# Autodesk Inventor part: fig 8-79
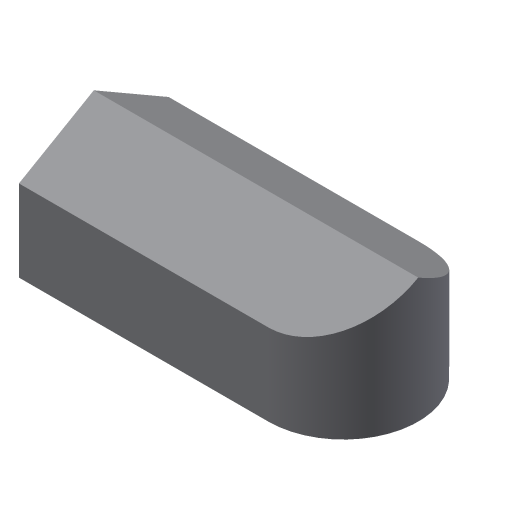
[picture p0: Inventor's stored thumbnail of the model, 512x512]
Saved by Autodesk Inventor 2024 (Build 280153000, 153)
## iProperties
Created: 2011-07
Part Number: fig 8-79
Material: Generic
Document SubType Name: Modeling
Designer: CadCim
Density: 1 g/cm^3
Appearance: Default
Author: CadCim
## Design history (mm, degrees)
sketch "Sketch1"
  geometry: L1 (-16, 5)-(-16, -7); L2 (-16, -7)-(4, -7); L3 (4, 5)-(-16, 5); A1 r 6 centre (4, -1) between (4, -7) and (4, 5); 1 further point
  constraints: 6 end point, 2 point on circle, 2 tangent, 1 centre point, 1 parallel, 1 perpendicular, 1 vertical
extrude "Extrusion1" new body sketch "Sketch1" distance "d0" = 10; taper "d1" = 0 deg
sketch "Sketch2"
  geometry: L1 (-16, -1)-(10, -1); 1 further point
  constraints: 2 end point, 1 horizontal
feature "FaceDraft1" sketch "Sketch2" dims angle "d2" = 30 deg
body "Solid1"
